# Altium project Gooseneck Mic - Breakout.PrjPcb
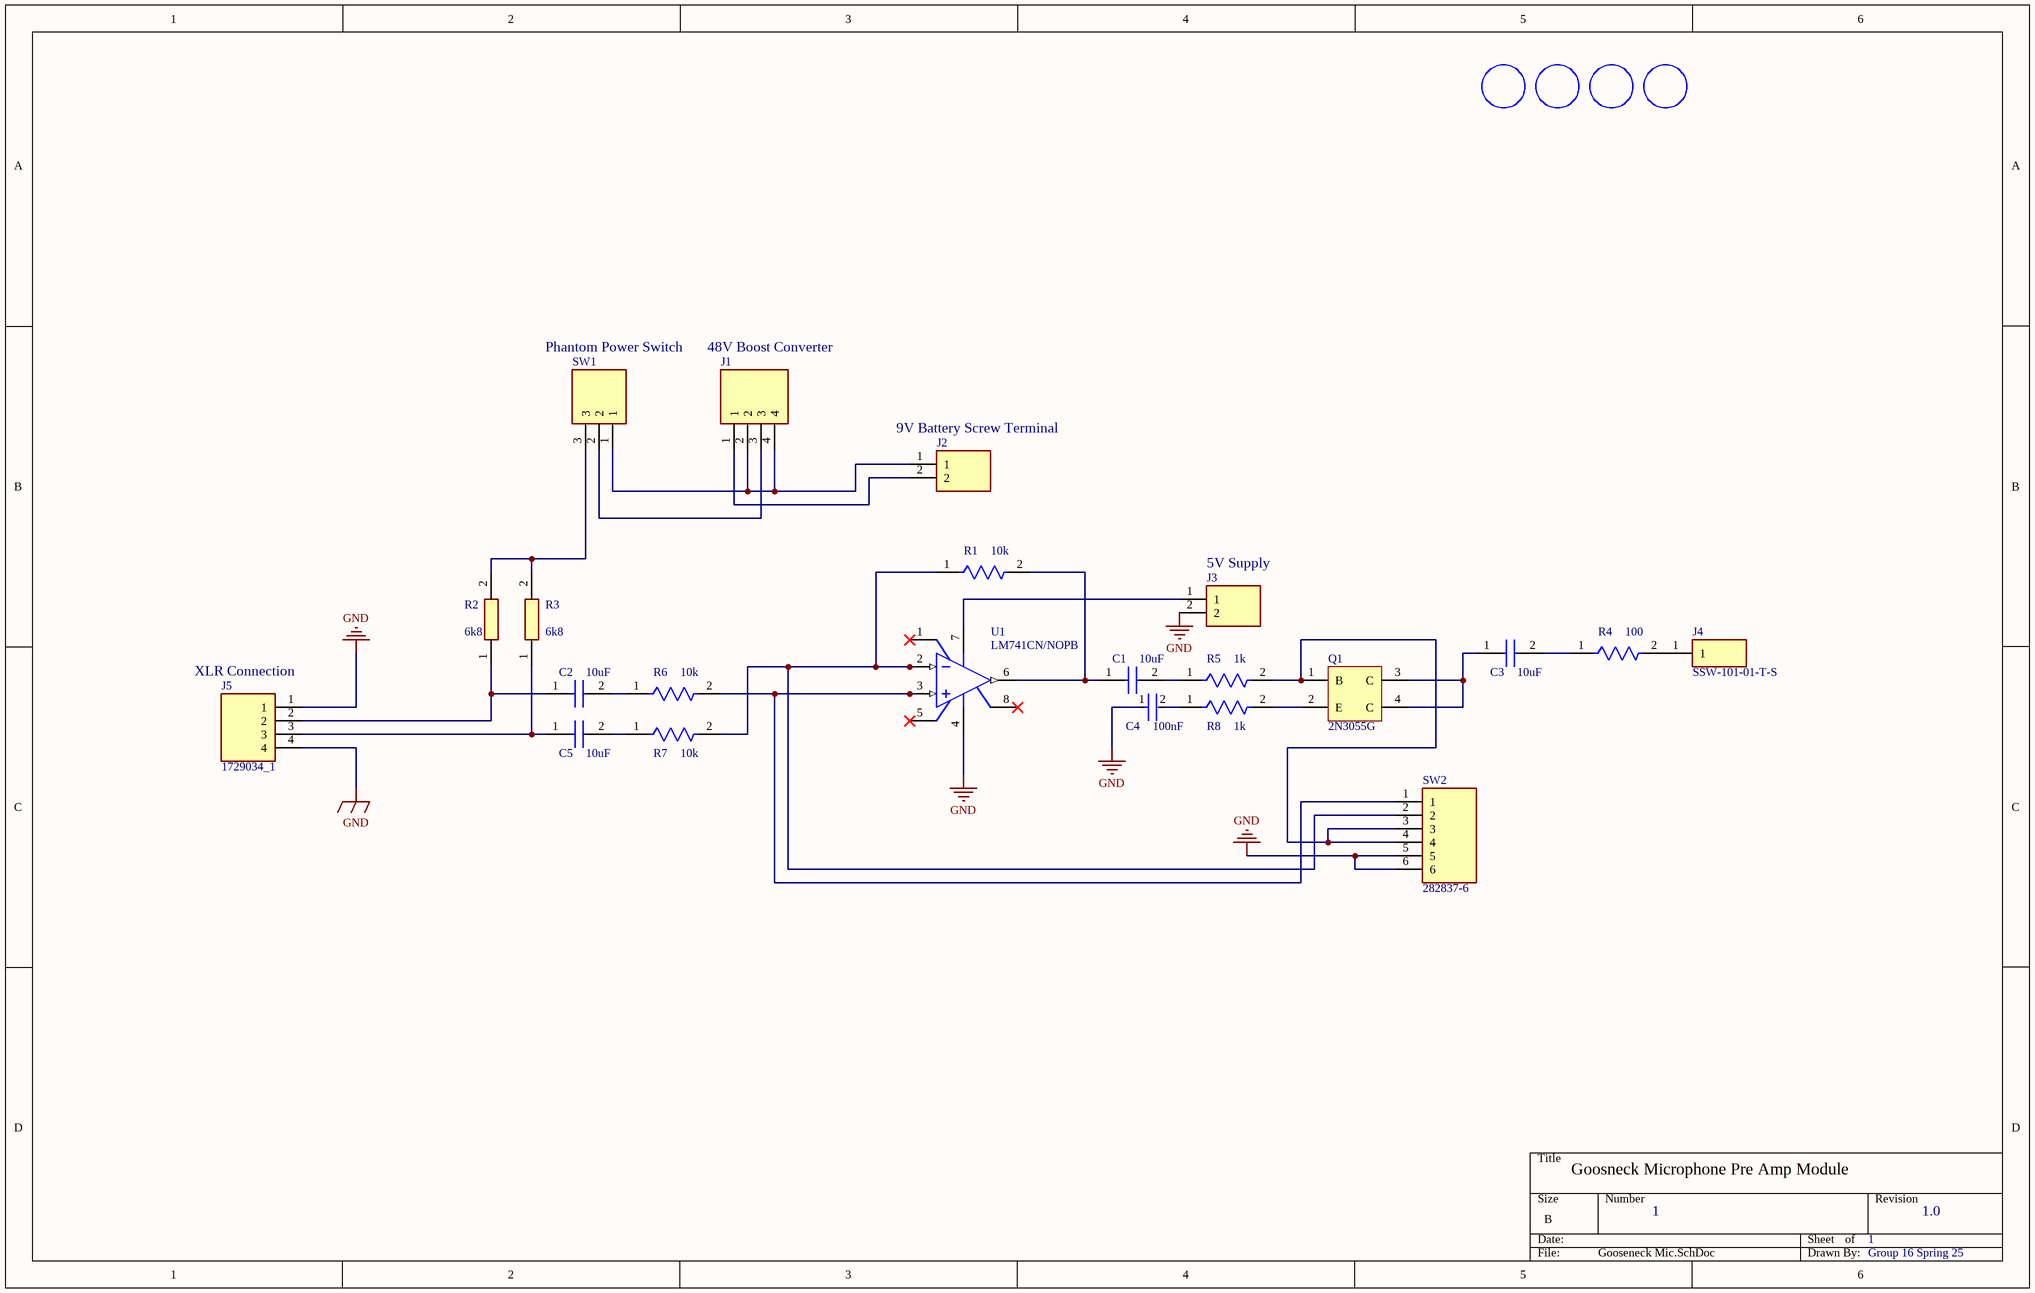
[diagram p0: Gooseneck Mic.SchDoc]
1 sheet, 26 parts. Net scope: global (net labels, ports and power ports of the same name join across sheets).
Board file: PCBGooseneck.PcbDoc

## Sheet Gooseneck Mic.SchDoc
size B; SheetNumber: 1; SheetTotal: 1

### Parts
C1  10uF  [FG20]
C2  10uF  [FG20]
C3  10uF  [FG20]
C4  100nF  [CAPRR508W50L508T317H508]
C5  10uF  [FG20]
J1  48V Boost Converter  [1729034]
J2  9V Battery Screw Terminal  [2828372]
J3  5V Supply  [2828372]
J4  SSW-101-01-T-S  [SSW-101-XX-YYY-S]
J5  1729034_1  [1729034]
MH1  Mounting Hole  [MTHNP3P2MM]  (value not drawn)
MH2  Mounting Hole  [MTHNP3P2MM]  (value not drawn)
MH3  Mounting Hole  [MTHNP3P2MM]  (value not drawn)
MH4  Mounting Hole  [MTHNP3P2MM]  (value not drawn)
Q1  2N3055G  [ONSC-TO-204-3-1-07]
R1  10k  [FP-RLR07-MFG]
R2  6k8  [RESAD1520W63L600D230]
R3  6k8  [RESAD1520W63L600D230]
R4  100  [FP-MRS25-MFG]
R5  1k  [FP-MRS25-MFG]
R6  10k  [FP-RLR07-MFG]
R7  10k  [FP-RLR07-MFG]
R8  1k  [FP-MRS25-MFG]
SW1  Phantom Power Switch  [RHDR3W80P0X254_1X3_812X254X850P]
SW2  282837-6  [2828376]
U1  LM741CN/NOPB  [P0008A]

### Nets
GND: C4.1 J3.2 J5.1 J5.4 SW2.5 SW2.6 U1.4(V-)
NetC1_1: C1.1 R1.2 U1.6(OUT)
NetC1_2: C1.2 R5.1
NetC2_1: C2.1 J5.2 R2.1
NetC2_2: C2.2 R6.1
NetC3_1: C3.1 Q1.3(C) Q1.4(C)
NetC3_2: C3.2 R4.1
NetC4_2: C4.2 R8.1
NetC5_1: C5.1 J5.3 R3.1
NetC5_2: C5.2 R7.1
NetJ1_1: J1.1 J2.2
NetJ1_2: J1.2 J1.4 J2.1 SW1.1
NetJ1_3: J1.3 SW1.2
NetJ3_1: J3.1 U1.7(V+)
NetJ4_1: J4.1 R4.2
NetQ1_1: Q1.1(B) R5.2 SW2.3 SW2.4
NetQ1_2: Q1.2(E) R8.2
NetR1_1: R1.1 R7.2 SW2.2 U1.2(IN-)
NetR2_2: R2.2 R3.2 SW1.3
NetR6_2: R6.2 SW2.1 U1.3(IN+)

Not connected (* = marked no-connect by the designer): U1 1(OFS_NULL)* 5(OFS_NULL)* 8(NC)*

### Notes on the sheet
- COLD end of mic is carried through inverting input of the LM741 op-amp. The HOT end of mic is carried through non-inverting input. The LM741 is Differential amplifier for balanced-to-single-ended conversion ~ asked Prof. Corey on 03/12 and he recommended this. The 2N3055 transistor provides high-current amplification.
- (near J5) XLR Connection
- (near C5) This is an NPN transistor configured in common emitter mode. The C57 is the coupling capacitor. It couples the input signal with the BE terminals of the transistor. The C57 capacitor in zero signal condition will work as an open circuit since the capacitor reactance is infinite at zero frequency ~ think "blocking capacitor." The C51 works as a coupling capacitor & feeds the amplified signal to form the output voltage ~ think "HOT END of mic."
- Normally closed - signal routes when switch is "off" so it cuts the audio signal ~ MUTE. Normally open is when switch is "on" so it sends signal to mic to audio processor. Common - where signal enters switch.
- Collector Pin > 10k to determine voltage drop across transistor and influence the gain of the amplifier. The amplified signal is taken from collector.
- OUT+ from Boost Converter and 9 V Battery > carries the HOT end of the mic > PIN 3 of XLR connector > Audio Processor
- 2N3055G NPN BJT transistor: classic power transistor used in linear and switching applications. 60 V capabilities, 15A current and 115W Power.
- First & Second Normally Closed (Pin 3 and 6) are grounded. First & Second Normally Open (Pin 2 and 5) are connected to 2N3055 emitter. The HOT XLR pin 3 is connected to first pole (toggle switch pin 1) & COLD XLR pin 2 is connected to second pole (toggle switch pin 4).
- Goosneck Microphone Pre Amp Module
- 1
- 1.0
- Group 16 Spring 25

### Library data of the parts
C1-C3 C5 = FG20X7R1H106KRT06: Capacitor FG20X7R1H106KRT06; Manufacturer_Name: TDK
C4 = b4654b650e69147ec39a6b967a45e02: CAP CER 0.1UF 50V X7R 0805 C0805C104K5RACTU High Frequency Noise Filtering; Manufacturer: KEMET; VALUE: 0.10 µF; Tolerance: 0.1; Temperature Coefficient: 30ppm/°C; Material: Ceramic
J1 = 1729034_1: Connector 1729034_1; Manufacturer_Name: Phoenix Contact
J2 J3 = 282837-2: Connector 282837-2; Manufacturer_Name: TE Connectivity
J4 = SSW-101-01-T-S: Connector; Manufacturer_Name: SAMTEC
J5 = 1729034_1: Connector; Manufacturer_Name: Phoenix Contact
Q1 = CMP-1048-01043-1: Complementary Silicon Power Transistor, 3-Pin TO-204, Pb-Free, Tray; Manufacturer: On Semiconductor; IC Continuous (A): 15; Polarity: NPN; fT Min (MHz): 2.5
R1 R6 R7 = CMP-00030-39449004-1: RLR07C1002FSB14 Fixed Resistor, Metal Film, 0.25W, 10000ohm, 250V, 1% +/-Tol, 100ppm/Cel, Through Hole Mount; Power Rating: 250mW; Lead Diameter: 640µm; Wire/Cable Diameter: 50.8µm; Lead Length: 38.1mm; Resistance: 10kΩ; Temperature Coefficient: 100ppm/°C
R2 R3 = CF14JT6K80_1: Resistor CF14JT6K80_1; Manufacturer_Name: Stackpole Electronics
R4 = CMP-00030-42757237-1: MRS25000C1000FRP00 Resistor, 100 Ohm, ± 1%, 600 mW, Axial Leaded, Metal Film (Thin Film), Professional; Max Power Dissipation: 600mW; Resistance: 100Ω; Voltage Rating: 350V; Temperature Coefficient: 50ppm/°C; Lead Diameter: 600µm
R5 R8 = CMP-02408-000051-1: RES 1K OHM 0.6W 1% AXIAL; Power Rating: 600mW; Lead Diameter: 0.6mm; Voltage Rating (DC): 350V; Resistance: 1kR; Temperature Coefficient: 50ppm/°C
SW1 = PPTC031LFBN-RC: Connector PPTC031LFBN-RC; Manufacturer_Name: Sullins
SW2 = 282837-6: Connector; Manufacturer_Name: TE Connectivity
U1 = CMP-0055-00162-3: Operational Amplifier, 8-pin MDIP, Pb-Free; Manufacturer: Texas Instruments; PackageTopMarking: NSUZXYTTE#*LM*741CN; PowerWise: N; CompType: Amplifiers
